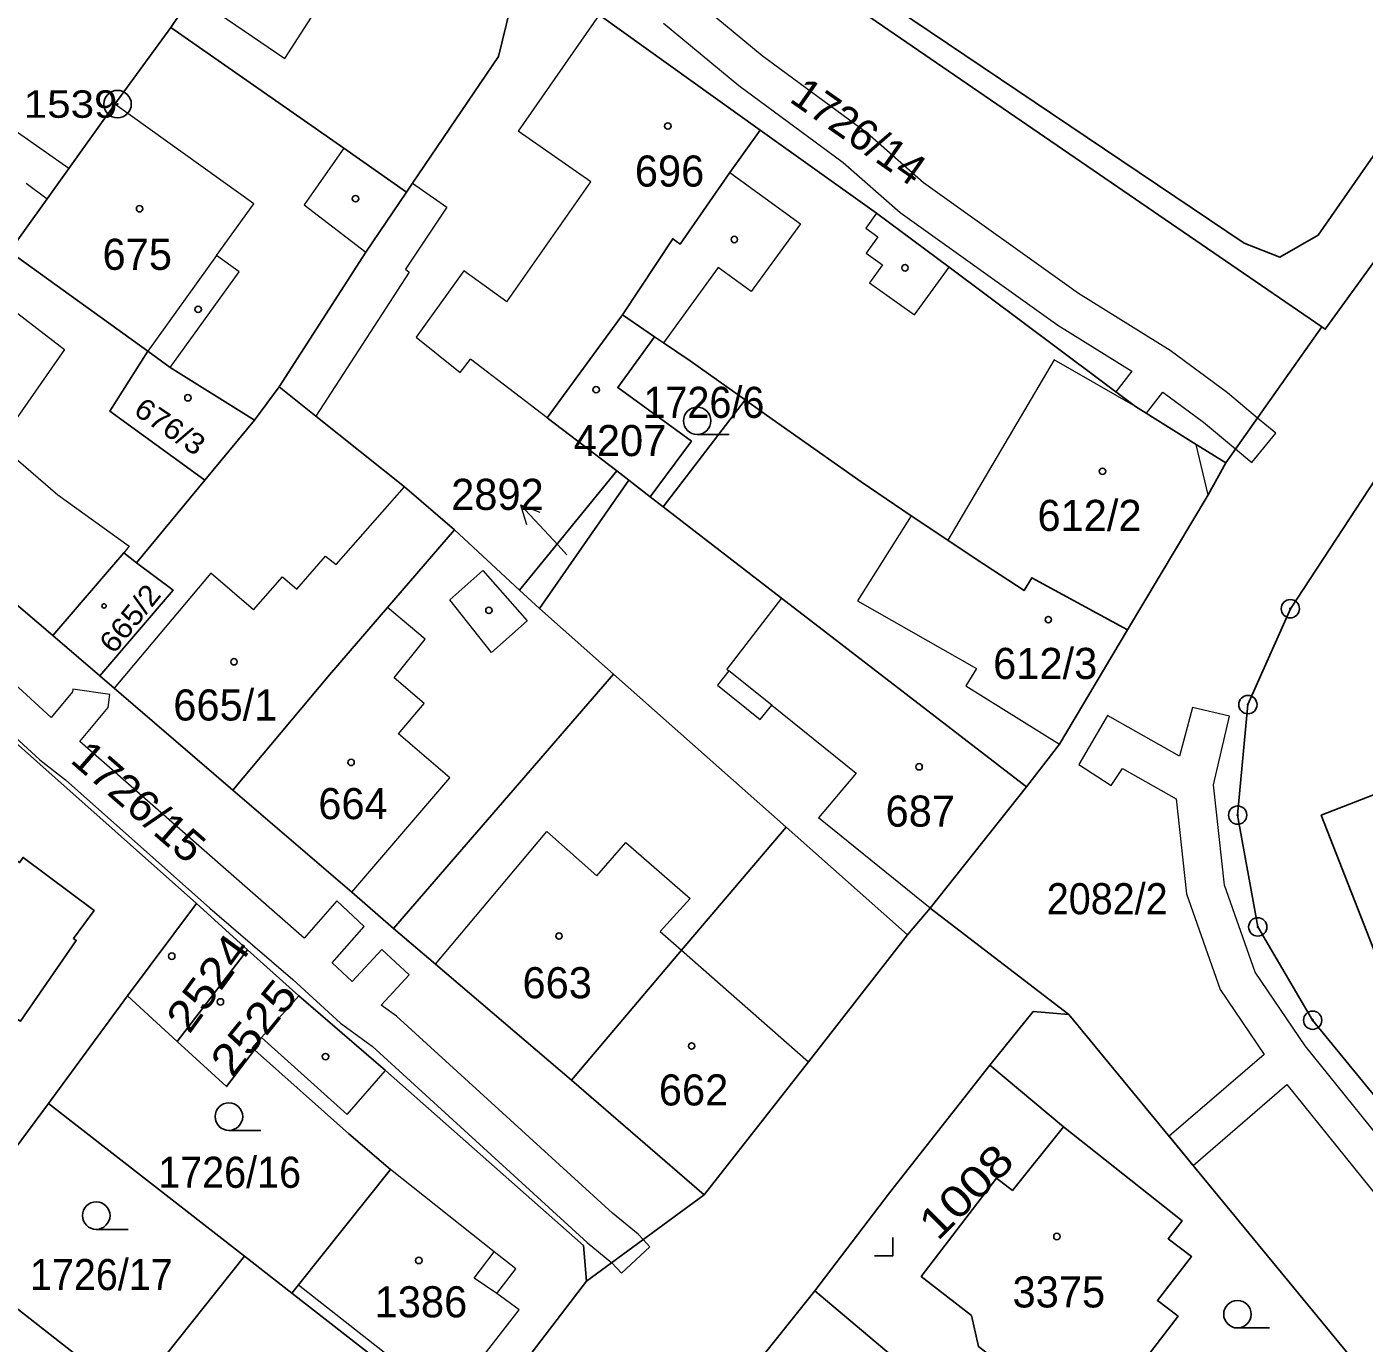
# Model space of a CAD drawing. Extents: x -679733 to -673243, y -1075091 to -1066557.
# Drawn here: x -676812 to -676738.9, y -1071988.2 to -1071916.2 of the extents above; entities that cross this region are included whole.
import ezdxf
from ezdxf.enums import TextEntityAlignment as Align

# ---------------------------------------------------------------- set-up
doc = ezdxf.new("R2010")
doc.units = 0
doc.header["$LTSCALE"] = 0.68
for name, color, linetype, lineweight in [('1', 7, 'Continuous', 25), ('13', 7, 'Continuous', 13), ('3', 7, 'Continuous', 25), ('4', 7, 'Continuous', 13), ('5', 7, 'Continuous', 25), ('7', 7, 'Continuous', 13), ('8', 7, 'Continuous', 25)]:
    doc.layers.add(name, color=color, linetype=linetype, lineweight=lineweight)
doc.layers.add('2', color=7, linetype='Continuous')

msp = doc.modelspace()

# ---------------------------------------------------------------- linework, layer by layer
at = {"layer": '1'}
for p, q in [((-676772.84, -1071909.65), (-676745.5, -1071928.08)), ((-676741.26, -1071932.65), (-676773.46, -1071910.57)), ((-676779.47, -1071931.99), (-676777.72, -1071933.19)), ((-676772.78, -1071936.63), (-676777.25, -1071942.48)), ((-676785.1, -1071947.04), (-676779.79, -1071940.52)), ((-676779.79, -1071940.52), (-676779.13, -1071941.03)), ((-676779.13, -1071941.03), (-676784.02, -1071948.04)), ((-676777.96, -1071941.93), (-676779.13, -1071941.03)), ((-676777.25, -1071942.48), (-676777.96, -1071941.93)), ((-676808.04, -1071951.72), (-676810.61, -1071949.51)), ((-676770.54, -1071959.99), (-676779.97, -1071951.63)), ((-676763.91, -1071965.87), (-676770.54, -1071959.99)), ((-676762.66, -1071964.41), (-676763.91, -1071965.87)), ((-676803.81, -1071971.7), (-676799.97, -1071966.7)), ((-676799.97, -1071966.7), (-676797.16, -1071969.21)), ((-676755.38, -1071976.37), (-676759.4, -1071972.99)), ((-676797.54, -1071985.46), (-676800.14, -1071983.43)), ((-676781.44, -1071984.81), (-676787.79, -1071993.08))]:
    msp.add_line(p, q, dxfattribs=at)
for points in [[(-676745.5, -1071928.08), (-676743.55, -1071928.83), (-676741.46, -1071927.63), (-676736.16, -1071920.02), (-676720.06, -1071896.06)], [(-676720.06, -1071896.06), (-676718.29, -1071897.33), (-676720.21, -1071902.35), (-676724.99, -1071910.57), (-676741.07, -1071932.78), (-676741.26, -1071932.65)], [(-676795.94, -1071904.8), (-676802.99, -1071914.53), (-676804.15, -1071916.28)], [(-676784.5, -1071913.06), (-676785.4, -1071914.35), (-676786.26, -1071917.87), (-676790.95, -1071924.8), (-676791.28, -1071925.28)], [(-676771.95, -1071921.89), (-676780.76, -1071915.59), (-676784.5, -1071913.06)], [(-676804.15, -1071916.28), (-676807.22, -1071920.47), (-676812.97, -1071928.53), (-676805.42, -1071933.98)], [(-676791.28, -1071925.28), (-676794.71, -1071922.88), (-676804.15, -1071916.28)], [(-676779.47, -1071931.99), (-676776.73, -1071927.83), (-676776.32, -1071928.12), (-676773.61, -1071924.21), (-676771.95, -1071921.89)], [(-676771.95, -1071921.89), (-676765.59, -1071926.44), (-676761.62, -1071929.38), (-676751.44, -1071936.99), (-676748.12, -1071939.07), (-676746.51, -1071940.08), (-676741.26, -1071932.65)], [(-676798.23, -1071935.93), (-676793.51, -1071928.56), (-676791.28, -1071925.28)], [(-676779.79, -1071940.52), (-676783.6, -1071937.61), (-676779.47, -1071931.99)], [(-676777.72, -1071933.19), (-676779.74, -1071935.96), (-676775.71, -1071938.9), (-676777.96, -1071941.93)], [(-676777.72, -1071933.19), (-676777.24, -1071933.51), (-676775.78, -1071934.5), (-676772.78, -1071936.63)], [(-676732.66, -1071981.65), (-676741.76, -1071970.54), (-676744.76, -1071965.44), (-676745.86, -1071959.33), (-676745.3, -1071953.29), (-676742.98, -1071948.05), (-676733.29, -1071933.3)], [(-676802.3, -1071941.03), (-676807.49, -1071937.26), (-676805.42, -1071933.98)], [(-676805.42, -1071933.98), (-676804.19, -1071934.87), (-676799.58, -1071937.75), (-676798.23, -1071935.93)], [(-676798.23, -1071935.93), (-676796.23, -1071937.53), (-676791.39, -1071941.39), (-676788.65, -1071943.74)], [(-676772.78, -1071936.63), (-676771.61, -1071937.47), (-676766.43, -1071941.12), (-676763.71, -1071942.98), (-676761.7, -1071944.3), (-676760.15, -1071945.35), (-676757.53, -1071947.06), (-676757.1, -1071946.36), (-676751.88, -1071949.2)], [(-676799.58, -1071937.75), (-676802.3, -1071941.03), (-676806.03, -1071945.54)], [(-676810.61, -1071949.51), (-676814.12, -1071946.52), (-676821.23, -1071940.32), (-676825.09, -1071945.59), (-676820.79, -1071949.33)], [(-676746.51, -1071940.08), (-676747.47, -1071941.82), (-676751.88, -1071949.2)], [(-676777.25, -1071942.48), (-676770.78, -1071947.47), (-676757.4, -1071957.79)], [(-676788.65, -1071943.74), (-676792.31, -1071947.99), (-676795.49, -1071951.67), (-676800.77, -1071957.97)], [(-676784.02, -1071948.04), (-676785.1, -1071947.04), (-676788.65, -1071943.74)], [(-676806.03, -1071945.54), (-676806.73, -1071944.99), (-676810.61, -1071949.51)], [(-676806.03, -1071945.54), (-676804.03, -1071947.04), (-676808.04, -1071951.72)], [(-676820.79, -1071949.33), (-676820.22, -1071948.63), (-676802.75, -1071964.16), (-676799.97, -1071966.7)], [(-676791.99, -1071965.52), (-676779.97, -1071951.63), (-676784.02, -1071948.04)], [(-676832.55, -1071956.32), (-676826.58, -1071960.72), (-676828.6, -1071963.46), (-676825.69, -1071965.33), (-676824.66, -1071963.73), (-676824.18, -1071962.99), (-676812.37, -1071970.59), (-676809.33, -1071966.18), (-676809.48, -1071966.07), (-676808.34, -1071964.55), (-676812.23, -1071961.64), (-676812.42, -1071961.92), (-676821.22, -1071955.8), (-676820.79, -1071949.33)], [(-676751.88, -1071949.2), (-676755.6, -1071955.45), (-676757.4, -1071957.79), (-676762.66, -1071964.41), (-676755.08, -1071970.22)], [(-676800.77, -1071957.97), (-676807.25, -1071952.4), (-676808.04, -1071951.72)], [(-676800.77, -1071957.97), (-676794.26, -1071963.54), (-676791.99, -1071965.52)], [(-676770.54, -1071959.99), (-676776.25, -1071966.72), (-676782.27, -1071973.81)], [(-676802.75, -1071964.16), (-676806.52, -1071969.21), (-676803.81, -1071971.7)], [(-676782.27, -1071973.81), (-676789.7, -1071967.47), (-676791.99, -1071965.52)], [(-676763.91, -1071965.87), (-676769.32, -1071972.82), (-676775.01, -1071980.08)], [(-676806.52, -1071969.21), (-676810.85, -1071975.09), (-676800.14, -1071983.43)], [(-676797.16, -1071969.21), (-676799.2, -1071971.49), (-676799.7, -1071972.05), (-676799.59, -1071972.15)], [(-676797.16, -1071969.21), (-676792.42, -1071973.28), (-676781.6, -1071982.86), (-676781.44, -1071984.81)], [(-676759.4, -1071972.99), (-676757.03, -1071970.07), (-676755.08, -1071970.22)], [(-676755.08, -1071970.22), (-676739.31, -1071989.39), (-676729.1, -1072001.75)], [(-676803.81, -1071971.7), (-676801.12, -1071974.17), (-676799.59, -1071972.15)], [(-676799.59, -1071972.15), (-676794.43, -1071976.75), (-676792.16, -1071978.69), (-676797.19, -1071985), (-676797.54, -1071985.46), (-676787.79, -1071993.08)], [(-676768.97, -1071985.33), (-676764.89, -1071979.98), (-676759.4, -1071972.99)], [(-676781.44, -1071984.81), (-676775.01, -1071980.08), (-676782.27, -1071973.81)], [(-676810.85, -1071975.09), (-676816.75, -1071983.04), (-676806.29, -1071991.21)], [(-676755.92, -1071990.16), (-676756.52, -1071989.71), (-676758.19, -1071989.79), (-676760.03, -1071988.38), (-676760.4, -1071986.68), (-676763.15, -1071984.54), (-676759.03, -1071979.17), (-676758.17, -1071979.84), (-676755.38, -1071976.37)], [(-676755.92, -1071990.16), (-676753.28, -1071992.14), (-676749.11, -1071986.72), (-676750.24, -1071985.85), (-676748.39, -1071983.45), (-676749.65, -1071982.48), (-676748.9, -1071981.5), (-676755.38, -1071976.37)], [(-676800.14, -1071983.43), (-676805.18, -1071989.78), (-676806.29, -1071991.21)], [(-676778.32, -1071997.1), (-676775.07, -1071992.96), (-676768.97, -1071985.33)], [(-676768.97, -1071985.33), (-676764.44, -1071989.13), (-676761.11, -1071991.92), (-676759.77, -1071993.04)]]:
    msp.add_lwpolyline(points, dxfattribs=at)
msp.add_lwpolyline([(-676730.02, -1071968.97), (-676731.31, -1071965.67), (-676737.81, -1071968.22), (-676741.29, -1071959.34), (-676729.95, -1071954.93), (-676725.19, -1071967.08)], close=True, dxfattribs=at)
at = {"layer": '13'}
for points in [[(-676777.23, -1071916.04), (-676773.12, -1071919.45), (-676767.41, -1071923.66), (-676764.3, -1071926.4), (-676755.69, -1071932.55), (-676751.64, -1071935.07), (-676752.51, -1071936.19), (-676751.44, -1071936.99), (-676750.84, -1071937.36), (-676749.94, -1071936.21), (-676747.73, -1071937.85), (-676745.98, -1071939.32), (-676745.08, -1071940.05), (-676743.78, -1071938.45), (-676744.78, -1071937.64), (-676746.41, -1071936.25), (-676749.55, -1071933.94), (-676754.55, -1071930.83), (-676763.02, -1071924.78), (-676766.11, -1071922.06), (-676771.84, -1071917.83), (-676775.85, -1071914.5)], [(-676812.07, -1071924.8), (-676810.92, -1071925.65), (-676809.73, -1071923.99), (-676812.54, -1071922.03)], [(-676814.49, -1071953.41), (-676811.31, -1071956.3), (-676809.91, -1071957.41), (-676802.03, -1071964.42), (-676797.49, -1071968.31), (-676794.89, -1071970.71), (-676793.16, -1071971.95), (-676781.41, -1071982.69), (-676780.06, -1071983.8), (-676779.53, -1071984.36), (-676777.99, -1071982.92), (-676778.34, -1071982.53), (-676778.62, -1071982.23), (-676780.03, -1071981.09), (-676791.82, -1071970.31), (-676792.66, -1071969.71), (-676791.13, -1071968.06), (-676792.63, -1071966.68), (-676794.25, -1071968.42), (-676795.35, -1071967.41), (-676793.59, -1071965.41), (-676795.09, -1071964.01), (-676796.87, -1071966.05), (-676809.14, -1071955.31), (-676807.59, -1071953.45), (-676807.49, -1071952.73), (-676809.51, -1071952.45), (-676809.53, -1071952.59), (-676810.7, -1071953.99), (-676813.85, -1071951.12)], [(-676708.44, -1072011.22), (-676709.73, -1072009.64), (-676710.89, -1072010.62), (-676729.48, -1071987.66), (-676728.4, -1071986.85), (-676729.7, -1071985.27), (-676730.76, -1071986.07), (-676742.17, -1071971.94), (-676744.91, -1071967.91), (-676746.57, -1071963.15), (-676747.17, -1071957.67), (-676746.3, -1071953.93), (-676748.32, -1071953.45), (-676749.04, -1071956.1), (-676752.97, -1071953.88), (-676754.54, -1071956.56)], [(-676754.54, -1071956.56), (-676752.78, -1071957.72), (-676752.15, -1071956.78), (-676749.22, -1071958.44), (-676748.65, -1071963.63), (-676746.81, -1071968.87), (-676744.41, -1071972.41), (-676749.61, -1071976.87), (-676748.29, -1071978.48), (-676743.18, -1071974.05), (-676731.79, -1071988.17)]]:
    msp.add_lwpolyline(points, dxfattribs=at)
at = {"layer": '3'}
for p, q in [((-676775.393, -1071938.53), (-676773.643, -1071938.53)), ((-676800.983, -1071976.56), (-676799.233, -1071976.56)), ((-676808.233, -1071981.97), (-676806.483, -1071981.97)), ((-676745.873, -1071987.36), (-676744.123, -1071987.36))]:
    msp.add_line(p, q, dxfattribs=at)
msp.add_lwpolyline([(-676765.701, -1071983.41), (-676764.7, -1071983.41), (-676764.7, -1071982.41)], dxfattribs=at)
for centre in [(-676775.3929, -1071937.7798), (-676800.9829, -1071975.8098), (-676808.2329, -1071981.2198), (-676745.8729, -1071986.6098)]:
    msp.add_circle(centre, 0.75, dxfattribs=at)
at = {"layer": '4'}
for p, q in [((-676797.92, -1071917.97), (-676794.86, -1071913.2)), ((-676802.99, -1071914.53), (-676797.92, -1071917.97)), ((-676780.76, -1071915.59), (-676785.18, -1071921.95)), ((-676799.63, -1071925.93), (-676807.22, -1071920.47)), ((-676781.2, -1071924.72), (-676785.18, -1071921.95)), ((-676794.71, -1071922.88), (-676796.88, -1071925.97)), ((-676773.61, -1071924.21), (-676769.75, -1071927.02)), ((-676790.95, -1071924.8), (-676789.07, -1071926.1)), ((-676785.8, -1071931.27), (-676781.2, -1071924.72)), ((-676801.66, -1071928.75), (-676799.63, -1071925.93)), ((-676796.88, -1071925.97), (-676793.51, -1071928.56)), ((-676789.07, -1071926.1), (-676791.33, -1071929.5)), ((-676765.59, -1071926.44), (-676766.18, -1071927.25)), ((-676769.75, -1071927.02), (-676772.44, -1071930.71)), ((-676766.18, -1071927.25), (-676765.52, -1071927.72)), ((-676765.52, -1071927.72), (-676766.16, -1071928.61)), ((-676801.66, -1071928.75), (-676805.42, -1071933.98)), ((-676800.42, -1071929.63), (-676801.66, -1071928.75)), ((-676766.16, -1071928.61), (-676765.27, -1071929.26)), ((-676804.19, -1071934.87), (-676800.42, -1071929.63)), ((-676791.33, -1071929.5), (-676791.13, -1071929.66)), ((-676788.15, -1071929.59), (-676790.76, -1071933.21)), ((-676785.8, -1071931.27), (-676788.15, -1071929.59)), ((-676774.24, -1071929.4), (-676777.24, -1071933.51)), ((-676772.44, -1071930.71), (-676774.24, -1071929.4)), ((-676765.27, -1071929.26), (-676765.97, -1071930.23)), ((-676763.52, -1071931.98), (-676761.62, -1071929.38)), ((-676791.13, -1071929.66), (-676796.23, -1071937.53)), ((-676765.97, -1071930.23), (-676763.52, -1071931.98)), ((-676814.34, -1071930.52), (-676809.97, -1071933.88)), ((-676809.97, -1071933.88), (-676813.57, -1071939.04)), ((-676783.6, -1071937.61), (-676787.78, -1071934.41)), ((-676755.89, -1071934.44), (-676761.7, -1071944.3)), ((-676751.44, -1071936.99), (-676755.89, -1071934.44)), ((-676813.57, -1071939.04), (-676810.33, -1071941.82)), ((-676747.47, -1071941.82), (-676748.12, -1071939.07)), ((-676810.33, -1071941.82), (-676806.43, -1071944.64)), ((-676795.13, -1071945.64), (-676791.39, -1071941.39)), ((-676763.71, -1071942.98), (-676766.63, -1071947.61)), ((-676806.43, -1071944.64), (-676806.73, -1071944.99)), ((-676797.27, -1071946.99), (-676795.71, -1071945.18)), ((-676795.71, -1071945.18), (-676795.13, -1071945.64)), ((-676801.98, -1071946.11), (-676807.25, -1071952.4)), ((-676799.65, -1071948.11), (-676801.98, -1071946.11)), ((-676799.65, -1071948.11), (-676798.06, -1071946.31)), ((-676798.06, -1071946.31), (-676797.27, -1071946.99)), ((-676788.92, -1071947.57), (-676787.11, -1071945.97)), ((-676787.11, -1071945.97), (-676784.68, -1071948.72)), ((-676786.64, -1071950.45), (-676788.92, -1071947.57)), ((-676770.78, -1071947.47), (-676773.78, -1071951.35)), ((-676766.63, -1071947.61), (-676760.13, -1071951.31)), ((-676790.26, -1071949.72), (-676792.31, -1071947.99)), ((-676784.68, -1071948.72), (-676786.64, -1071950.45)), ((-676773.66, -1071951.44), (-676774.29, -1071952.22)), ((-676773.78, -1071951.35), (-676773.66, -1071951.44)), ((-676771.32, -1071953.32), (-676773.66, -1071951.44)), ((-676760.13, -1071951.31), (-676760.72, -1071952.26)), ((-676774.29, -1071952.22), (-676771.95, -1071954.1)), ((-676760.72, -1071952.26), (-676755.6, -1071955.45)), ((-676791.72, -1071954.89), (-676790.31, -1071953.23)), ((-676771.95, -1071954.1), (-676771.32, -1071953.32)), ((-676771.32, -1071953.32), (-676766.71, -1071957.03)), ((-676788.91, -1071957.29), (-676791.72, -1071954.89)), ((-676794.26, -1071963.54), (-676788.91, -1071957.29)), ((-676766.71, -1071957.03), (-676768.77, -1071959.48)), ((-676762.66, -1071964.41), (-676768.77, -1071959.48)), ((-676789.7, -1071967.47), (-676783.62, -1071960.22)), ((-676783.62, -1071960.22), (-676780.88, -1071962.64)), ((-676780.88, -1071962.64), (-676779.29, -1071960.82)), ((-676779.29, -1071960.82), (-676775.78, -1071963.89)), ((-676775.78, -1071963.89), (-676777.42, -1071965.69)), ((-676777.42, -1071965.69), (-676776.25, -1071966.72)), ((-676776.25, -1071966.72), (-676769.32, -1071972.82)), ((-676799.2, -1071971.49), (-676794.52, -1071975.7)), ((-676794.52, -1071975.7), (-676792.42, -1071973.28)), ((-676786.49, -1071983.2), (-676792.16, -1071978.69)), ((-676787.59, -1071984.63), (-676786.49, -1071983.2)), ((-676785.3, -1071984.12), (-676786.49, -1071983.2)), ((-676786.34, -1071985.47), (-676785.3, -1071984.12)), ((-676797.19, -1071985), (-676789.04, -1071991.38)), ((-676786.34, -1071985.47), (-676787.59, -1071984.63)), ((-676785.13, -1071986.37), (-676786.34, -1071985.47)), ((-676789.04, -1071991.38), (-676785.13, -1071986.37))]:
    msp.add_line(p, q, dxfattribs=at)
for points in [[(-676790.76, -1071933.21), (-676788.34, -1071935.14), (-676787.78, -1071934.41)], [(-676790.31, -1071953.23), (-676791.96, -1071951.82), (-676790.26, -1071949.72)]]:
    msp.add_lwpolyline(points, dxfattribs=at)
at = {"layer": '5'}
for centre, radius in [((-676776.9968, -1071921.6692), 0.175), ((-676794.0668, -1071925.6392), 0.175), ((-676805.8668, -1071926.1892), 0.175), ((-676773.3668, -1071927.8692), 0.175), ((-676764.0368, -1071929.4192), 0.175), ((-676802.6668, -1071931.6892), 0.175), ((-676780.9168, -1071936.0792), 0.175), ((-676803.2268, -1071936.5192), 0.175), ((-676753.2468, -1071940.5392), 0.175), ((-676807.8046, -1071947.8994), 0.1172), ((-676786.7768, -1071948.1392), 0.175), ((-676756.2068, -1071948.6492), 0.175), ((-676800.7068, -1071950.9492), 0.175), ((-676794.3068, -1071956.4492), 0.175), ((-676763.2668, -1071956.6892), 0.175), ((-676782.9468, -1071965.9392), 0.175), ((-676804.1068, -1071967.0392), 0.175), ((-676801.4468, -1071969.5392), 0.175), ((-676775.6968, -1071971.9492), 0.175), ((-676795.7068, -1071972.5292), 0.175), ((-676755.7368, -1071982.3592), 0.175), ((-676790.6068, -1071983.6692), 0.175)]:
    msp.add_circle(centre, radius, dxfattribs=at)
at = {"layer": '7'}
msp.add_line((-676785.047, -1071942.375), (-676784.73, -1071943.449), dxfattribs=at)
msp.add_lwpolyline([(-676782.51, -1071945.11), (-676783, -1071944.57), (-676785.047, -1071942.375), (-676783.997, -1071942.766)], dxfattribs=at)
at = {"layer": '8'}
for centre, radius in [((-676807.07, -1071920.4698), 0.75), ((-676807.07, -1071920.4698), 0.03), ((-676742.98, -1071948.0499), 0.5), ((-676742.98, -1071948.0499), 0.0303), ((-676745.3, -1071953.2899), 0.5), ((-676745.3, -1071953.2899), 0.0303), ((-676745.86, -1071959.3299), 0.5), ((-676745.86, -1071959.3299), 0.0303), ((-676744.76, -1071965.4399), 0.5), ((-676744.76, -1071965.4399), 0.0303), ((-676741.76, -1071970.5399), 0.5), ((-676741.76, -1071970.5399), 0.0303)]:
    msp.add_circle(centre, radius, dxfattribs=at)

# ---------------------------------------------------------------- texts
at = {"layer": '2'}
msp.add_text('1726/14', height=1.7, rotation=325, dxfattribs=at).set_placement((-676770.417, -1071920.296))
for s, p in [('696', (-676778.8, -1071924.979)), ('675', (-676807.89, -1071929.529)), ('612/2', (-676756.8, -1071943.8)), ('612/3', (-676759.22, -1071951.89)), ('664', (-676796.1, -1071959.55)), ('687', (-676765.1, -1071959.96)), ('663', (-676784.94, -1071969.34)), ('662', (-676777.49, -1071975.2)), ('1386', (-676793.02, -1071986.779)), ('3375', (-676758.16, -1071986.239))]:
    msp.add_text(s, height=1.7, dxfattribs=at).set_placement(p)
at = {"layer": '2', "width": 0.95}
for s, p in [('1726/6', (-676778.33, -1071937.62)), ('2082/2', (-676756.29, -1071964.749)), ('1726/16', (-676804.85, -1071979.7)), ('1726/17', (-676811.86, -1071985.29))]:
    msp.add_text(s, height=1.7, dxfattribs=at).set_placement(p)
at = {"layer": '2'}
for s, height, rotation, width, p in [('676/3', 1.14, 326, 1.1, (-676806.258, -1071937.382)), ('1726/15', 1.7, 319, 1.05, (-676809.717, -1071956.401)), ('2524', 1.7, 54, 1.15, (-676803.152, -1071971.349)), ('2525', 1.7, 51, 1.15, (-676800.799, -1071973.734)), ('1008', 1.7, 45, 1.2, (-676762.248, -1071982.651))]:
    msp.add_text(s, height=height, rotation=rotation, dxfattribs=dict(at, width=width)).set_placement(p)
for s, p in [('4207', (-676779.61, -1071939.71)), ('2892', (-676786.31, -1071942.65)), ('665/1', (-676801.18, -1071954.16))]:
    msp.add_text(s, height=1.7, dxfattribs=at).set_placement(p, align=Align.CENTER)
at = {"layer": '2', "width": 1.1}
msp.add_text('665/2', height=1.14, rotation=51, dxfattribs=at).set_placement((-676805.9531, -1071948.9397), align=Align.CENTER)
at = {"layer": '8', "width": 1.15}
msp.add_text('1539', height=1.5, dxfattribs=at).set_placement((-676807.069, -1071921.22), align=Align.RIGHT)

doc.saveas('drawing.dxf')
